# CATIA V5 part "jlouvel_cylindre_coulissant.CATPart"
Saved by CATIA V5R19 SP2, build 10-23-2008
Part number: Pièce 5_cylindre coulissant
Bounding box of the stored display mesh (mm): x -9.942 to 15, y -15 to 15, z -9.942 to 9.942
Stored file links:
  E:\IAO_2010\iao\IAO_MMS_Groupe2\IAO_MMS_Groupe2\OK\jlouvel\jlouvel_iao\pièces cao catia ifma\jlouvel_cylindre_coulissant.CATPart
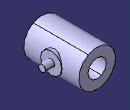
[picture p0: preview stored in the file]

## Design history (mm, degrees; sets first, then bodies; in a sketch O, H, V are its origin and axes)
Body1 (main body)
  Sketch1 on yz-plane, origin (0, 0, 0), H (0, 1, 0), V (0, 0, 1)
    line L1 (-15, 5) -> (15, 5)
    line L2 (15, 5) -> (15, 10)
    line L3 (15, 10) -> (-15, 10)
    line L4 (-15, 10) -> (-15, 5)
    length L3 = 30
    length L2 = 5
    distance H L1 = 5
    horizontal: L1 H, L3 H
    vertical: L2 V, L4 V
    symmetry: L2 L4 V
  Shaft1: profile Sketch1, axis Sketch1.H, angle 360
  Plane1: type Offset, RefPlane yz-plane, Offset 10
  Sketch2 on Plane1, origin (10, 0, 0), H (0, 1, 0), V (0, 0, 1)
    circle A1 centre (0, 0) radius 2
    reference projected line E1 through (0, 0) direction (1, 0) from axis of face of Shaft1 from Sketch1.L3
    distance A1 E1 = 0 (reference)
  Pad1: profile Sketch2, direction (1, 0, 0), length 5
  Sketch3 on Plane1, origin (10, 0, 0), H (0, 1, 0), V (0, 0, 1)
    circle A1 centre (0, 0) radius 5.7759
  Pad2: profile Sketch3, direction (-1, 0, 0), length 2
